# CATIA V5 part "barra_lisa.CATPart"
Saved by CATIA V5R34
Part number: barra_lisa
Bounding box of the stored display mesh (mm): x -4 to 4, y -3.991 to 3.991, z -175 to 175
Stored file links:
  C:\Users\Apolinar\Desktop\cnc\barra_lisa.CATPart
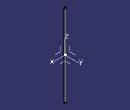
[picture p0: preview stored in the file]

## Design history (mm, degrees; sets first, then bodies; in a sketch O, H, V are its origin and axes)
AxisSystem1: origin (0, 0, 0), X (1, 0, 0), Y (0, 1, 0), Z (0, 0, 1)
Body1 (main body)
  Sketch1 on XY plane of AxisSystem1, origin (0, 0, 0), H (1, 0, 0), V (0, 1, 0)
    circle A1 centre (0, 0) radius 4
    radius A1 = 4
  Pad1: profile Sketch1, direction (0, 0, 1), length 175, mirrored extent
